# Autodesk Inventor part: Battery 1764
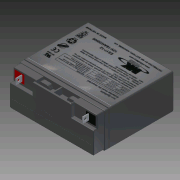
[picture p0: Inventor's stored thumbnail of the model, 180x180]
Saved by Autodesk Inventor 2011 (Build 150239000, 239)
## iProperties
Created: 2008-01
Part Number: Battery 1764
Document SubType Name: Modeling
Designer: rlindsay
Density: 1 g/cm^3
Author: rlindsay
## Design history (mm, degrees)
sketch "Sketch1"
  geometry: L1 (-28.148, 47.877)-(149.652, 47.877); L2 (149.652, 47.877)-(149.652, -25.148); L3 (149.652, -25.148)-(-28.148, -25.148); L4 (-28.148, -25.148)-(-28.148, 47.877)
  constraints: 8 end point, 2 parallel, 1 horizontal, 1 perpendicular
  dimensions: "d0" = 73.025 distance of L3.end L1.start; "d1" = 177.8 distance of L2.end L3.end
extrude "Extrusion1" new body sketch "Sketch1" distance "d2" = 165.1; taper "d3" = 0 deg
workplane "Work Plane1"
sketch "Sketch6"
  geometry: L1 (177.8, 0)-(177.8, -152.4); L2 (0, 0)-(0, -152.4); L3 (177.8, -128.392)-(-149.757, -128.392); L4 (-149.757, -128.392)-(-149.757, 18.237); L5 (-149.757, 18.237)-(177.8, 18.237); L6 (177.8, 18.237)-(177.8, -128.392); 1 other entity
  constraints: 4 end point, 2 other
  dimensions: "d70" = 180 deg angle of L1 L6
feature "Decal2" sketch "Sketch6"
sketch "Sketch7"
  geometry: L1 (177.8, 0)-(177.8, -165.1) reference; L2 (0, 0)-(0, -165.1) reference; L3 (177.8, -135.89)-(0, -135.89); L4 (0, -135.89)-(0, -134.112); L5 (0, -134.112)-(177.8, -134.112); L6 (177.8, -134.112)-(177.8, -135.89); L7 (0, -165.1)-(177.8, -165.1) reference; L8 (0, 0)-(177.8, 0) reference
  constraints: 8 end point, 2 parallel, 2 point on line, 1 horizontal, 1 perpendicular
  dimensions: "d99" = 1.778 distance between parallel lines of L5 L3
extrude "Extrusion5" cut sketch "Sketch7" distance "d101" = 1.778; taper "d102" = 0 deg
sketch "Sketch8"
  geometry: L1 (0, 0)-(165.1, 0) reference; L2 (135.89, 73.025)-(135.89, 71.247) reference; L3 (134.112, 73.025)-(135.89, 73.025); L4 (135.89, 73.025)-(135.89, 0); L5 (135.89, 0)-(134.112, 0); L6 (134.112, 0)-(134.112, 73.025)
  constraints: 8 end point, 2 parallel, 1 horizontal, 1 perpendicular, 1 point on line
  dimensions: "d103" = 0 distance between parallel lines of L4 L2
extrude "Extrusion6" cut sketch "Sketch8" distance "d104" = 1.778; taper "d105" = 0 deg
sketch "Sketch9"
  geometry: L1 (0, 135.89)-(1.778, 135.89) reference; L2 (177.8, 0)-(177.8, 165.1) reference; L3 (0, 134.112)-(177.8, 134.112); L4 (177.8, 134.112)-(177.8, 135.89); L5 (177.8, 135.89)-(0, 135.89); L6 (0, 135.89)-(0, 134.112)
  constraints: 8 end point, 2 parallel, 1 horizontal, 1 perpendicular, 1 point on line
  dimensions: "d106" = 0 distance between parallel lines of L5 L1
extrude "Extrusion7" cut sketch "Sketch9" distance "d107" = 1.778; taper "d108" = 0 deg
sketch "Sketch10"
  geometry: L1 (-135.89, 73.025)-(-134.112, 73.025); L2 (-134.112, 73.025)-(-134.112, 0); L3 (-134.112, 0)-(-135.89, 0); L4 (-135.89, 0)-(-135.89, 73.025)
  constraints: 8 end point, 2 parallel, 1 horizontal, 1 perpendicular
extrude "Extrusion8" cut sketch "Sketch10" distance "d109" = 1.778; taper "d110" = 0 deg
sketch "Sketch11"
  geometry: L1 (177.8, 29.21)-(0, 29.21) reference; L2 (0, 29.21)-(0, 0) reference; L3 (177.8, 29.21)-(177.8, 0) reference; L4 (127, 21.336)-(90.17, 21.336); L5 (90.17, 21.336)-(90.17, 0); L6 (90.17, 0)-(127, 0); L7 (127, 0)-(127, 21.336); L8 (87.63, 0)-(50.8, 0); L9 (50.8, 0)-(50.8, 21.336); L10 (50.8, 21.336)-(87.63, 21.336); L11 (87.63, 21.336)-(87.63, 0); L12 (0, 0)-(177.8, 0) reference
  constraints: 16 end point, 4 parallel, 2 horizontal, 2 perpendicular
  dimensions: "d111" = 7.874 distance between parallel lines of L1 L10; "d112" = 7.874 distance between parallel lines of L1 L4; "d113" = 50.8 distance between parallel lines of L3 L7; "d115" = 0 distance between parallel lines of L6 L8; "d116" = 50.8 distance between parallel lines of L9 L2; "d117" = 36.83 distance of L8.start L8.end; "d121" = 36.83 distance between parallel lines of L5 L7; "d122" = 0 distance between parallel lines of L12 L8
extrude "Extrusion9" cut sketch "Sketch11" distance "d119" = 13.97; taper "d120" = 0 deg
sketch "Sketch13"
  geometry: L1 (36.83, -13.97)-(0, -13.97) reference; L2 (36.83, 0)-(36.83, -13.97) reference; L3 (0, 0)-(36.83, 0) reference; L4 (0, 0)-(0, -13.97) reference; L5 (-49.276, -1.524)-(125.476, -1.524); L6 (125.476, -1.524)-(125.476, -71.501); L7 (125.476, -71.501)-(-49.276, -71.501); L8 (-49.276, -71.501)-(-49.276, -1.524); L9 (127, 0)-(127, -73.025) reference; L10 (127, -73.025)-(-50.8, -73.025) reference; L11 (-50.8, -73.025)-(-50.8, 0) reference; L12 (-50.8, 0)-(127, 0); L13 (127, 0)-(127, -73.025); L14 (127, -73.025)-(-50.8, -73.025); L15 (-50.8, -73.025)-(-50.8, 0)
  constraints: 16 end point, 4 parallel, 2 horizontal, 2 perpendicular
  dimensions: "d123" = 1.524 distance between parallel lines of L3 L5; "d124" = 1.524 distance between parallel lines of L9 L6; "d125" = 1.524 distance between parallel lines of L10 L7; "d126" = 1.524 distance between parallel lines of L11 L8; "d127" = 0 distance between parallel lines of L9 L13
extrude "Extrusion10" cut sketch "Sketch13" stored distance "d128" = 7.62; taper "d129" = 0 deg
sketch "Sketch14"
  geometry: L1 (148.128, -23.624)-(148.128, 46.353) reference; L2 (148.128, 46.353)-(98.852, 46.353) reference; L3 (-26.624, 46.353)-(20.366, 46.353); L4 (20.366, 46.353)-(20.366, 21.715); L5 (20.366, 21.715)-(-26.624, 21.715); L6 (-26.624, 21.715)-(-26.624, 46.353); L7 (101.138, 46.353)-(148.128, 46.353); L8 (148.128, 46.353)-(148.128, 21.715); L9 (148.128, 21.715)-(101.138, 21.715); L10 (101.138, 21.715)-(101.138, 46.353)
  constraints: 16 end point, 4 parallel, 2 horizontal, 2 perpendicular
  dimensions: "d130" = 46.99 distance of L4.end L5.end; "d131" = 24.638 distance of L3.end L4.end; "d132" = 0 distance between parallel lines of L2 L7; "d133" = 0 distance between parallel lines of L1 L8; "d134" = 24.638 distance of L9.end L7.start; "d135" = 46.99 distance of L8.end L9.end
extrude "Extrusion11" cut sketch "Sketch14" distance "d136" = 7.239; taper "d137" = 0 deg
sketch "Sketch15"
  geometry: L1 (-26.624, 46.353)-(20.366, 46.353) reference; L2 (-26.624, 21.715)-(-26.624, 46.353) reference; L3 (-23.322, 43.051)-(-3.002, 43.051); L4 (-3.002, 43.051)-(-3.002, 25.271); L5 (-3.002, 25.271)-(-23.322, 25.271); L6 (-23.322, 25.271)-(-23.322, 43.051); L7 (148.128, 46.353)-(148.128, 21.715) reference; L8 (101.138, 46.353)-(148.128, 46.353) reference
  constraints: 8 end point, 2 parallel, 1 horizontal, 1 perpendicular
  dimensions: "d138" = 3.302 distance between parallel lines of L1 L3; "d139" = 20.32 distance of L4.end L5.end; "d140" = 3.302 distance between parallel lines of L2 L6; "d141" = 17.78 distance of L3.end L4.end
extrude "Extrusion12" cut sketch "Sketch15" distance "d146" = 0.254; taper "d147" = 0 deg
sketch "Sketch16"
  geometry: L1 (148.128, 46.353)-(148.128, 21.715) reference; L2 (124.506, 25.017)-(144.826, 25.017); L3 (144.826, 25.017)-(144.826, 42.797); L4 (144.826, 42.797)-(124.506, 42.797); L5 (124.506, 42.797)-(124.506, 25.017); L6 (-26.37, 46.099)-(147.874, 46.099) reference
  constraints: 8 end point, 2 parallel, 1 horizontal, 1 perpendicular
  dimensions: "d148" = 3.302 distance between parallel lines of L6 L4; "d149" = 3.302 distance between parallel lines of L1 L3; "d150" = 17.78 distance of L4.end L2.start; "d151" = 20.32 distance of L3.end L4.end
extrude "Extrusion13" cut sketch "Sketch16" distance "d152" = 0.0254; taper "d153" = 0 deg
sketch "Sketch17"
  geometry: L1 (101.138, 46.353)-(98.852, 46.353) reference; L2 (62.022, 33.907)-(62.022, 46.353) reference; L3 (59.482, 46.353)-(59.482, 33.907) reference; L4 (22.652, 46.353)-(20.366, 46.353) reference; L5 (22.652, 33.907)-(40.432, 33.907); L6 (40.432, 33.907)-(40.432, 28.573); L7 (40.432, 28.573)-(22.652, 28.573); L8 (22.652, 28.573)-(22.652, 33.907); L9 (98.852, 33.907)-(81.072, 33.907); L10 (81.072, 33.907)-(81.072, 28.573); L11 (81.072, 28.573)-(98.852, 28.573); L12 (98.852, 28.573)-(98.852, 33.907)
  constraints: 16 end point, 4 parallel, 2 horizontal, 2 perpendicular
  dimensions: "d157" = 17.78 distance between parallel lines of L4 L7; "d158" = 19.05 distance between parallel lines of L3 L6; "d159" = 17.78 distance between parallel lines of L1 L11; "d160" = 19.05 distance between parallel lines of L2 L10
extrude "Extrusion14" cut sketch "Sketch17" stored distance "d161" = 25.4; taper "d162" = 0 deg
sketch "Sketch18"
  geometry: L1 (-26.624, 21.715)-(-26.624, -23.624) reference; L2 (-26.624, -23.624)-(148.128, -23.624) reference; L3 (148.128, -23.624)-(148.128, 21.715) reference; L4 (145.334, -5.844)-(-23.83, -5.844); L5 (-23.83, -5.844)-(-23.83, 18.921); L6 (-23.83, 18.921)-(145.334, 18.921); L7 (145.334, 18.921)-(145.334, -5.844)
  constraints: 8 end point, 2 parallel, 1 horizontal, 1 perpendicular
  dimensions: "d163" = 2.794 distance between parallel lines of L1 L5; "d164" = 2.794 distance between parallel lines of L3 L7; "d165" = 17.78 distance between parallel lines of L2 L4; "d166" = 24.765 distance between parallel lines of L4 L6
extrude "Extrusion15" cut sketch "Sketch18" distance "d167" = 0.127; taper "d168" = 0 deg
sketch "Sketch19"
  geometry: L1 (62.889, 3.821)-(38.353, 3.821); L2 (38.353, 3.821)-(38.353, 8.511); L3 (38.353, 8.511)-(62.889, 8.511); L4 (62.889, 8.511)-(62.889, 3.821)
  constraints: 2 other
extrude "Extrusion16" cut sketch "Sketch19" distance "d169" = 0.127; taper "d170" = 0 deg
sketch "Sketch20"
  geometry: L1 (50.8, -1.524)-(50.8, -19.304) reference; L2 (87.63, -1.524)-(87.63, -13.97) reference; L3 (0, 0)-(177.8, 0) reference; L4 (70.739, -21.658)-(52.705, -21.658); L5 (54.61, -5.842)-(70.739, -5.842); L6 (70.739, -5.842)-(70.739, -21.658); L7 (109.22, -19.304)-(127, -19.304) reference; L8 (125.095, -5.842)-(125.095, -19.304); L9 (125.095, -19.304)-(107.061, -19.304); L10 (50.8, -19.304)-(68.58, -19.304) reference; L11 (48.266, -11.928)-(48.266, -19.304); L12 (48.266, -19.304)-(50.8, -19.304); L13 (48.266, -19.304)-(70.739, -19.304); A1 r 6.35 centre (54.61, -12.192) between (54.912, -5.849) and (48.266, -11.928)
  constraints: 16 end point, 3 perpendicular, 3 point on circle, 3 point on line, 2 collinear, 1 centre point, 1 horizontal, 1 parallel
  dimensions: "d171" = 16.891 distance between parallel lines of L2 L6; "d173" = 5.842 distance between parallel lines of L3 L5; "d185" = 6.35 radius of A1; "d186" = 6.35 distance from line of L5 A1.centre; "d187" = 3.81 distance from line of L1 A1.centre
extrude "Extrusion17" join sketch "Sketch20" distance "d176" = 8.128; taper "d177" = 0 deg
sketch "Sketch21"
  geometry: L1 (22.652, 46.353)-(98.852, 46.353); L2 (98.852, 46.353)-(98.852, 28.573); L3 (98.852, 28.573)-(22.652, 28.573); L4 (22.652, 28.573)-(22.652, 46.353)
  constraints: 8 end point, 2 parallel, 1 horizontal, 1 perpendicular
extrude "Extrusion18" join sketch "Sketch21" distance "d178" = 3.048; taper "d179" = 0 deg
fillet "Fillet4" dims "d181" = 6.35
workplane "Work Plane2"
mirror "Mirror1"
fillet "Fillet5" dims "d189" = 6.35
fillet "Fillet6" dims "d190" = 2.54
fillet "Fillet7" dims "d191" = 1.27
sketch "Sketch23"
  geometry: L1 (-3.002, 43.051)-(-3.002, 25.271) reference; L2 (-26.37, 46.099)-(147.874, 46.099) reference; C1 r 3.81 at (7.158, 34.669); C2 r 4.28 at (112.672, 32.669)
  constraints: 2 centre point
  dimensions: "d192" = 11.43 distance from line of L2 C1.centre; "d193" = 10.16 distance from line of L1 C1.centre; "d194" = 7.62 diameter of C1
extrude "Extrusion19" cut sketch "Sketch23" distance "d195" = 0.0508; taper "d196" = 0 deg
mirror "Mirror2"
sketch "Sketch24"
  geometry: L1 (-0.635, 5.715)-(-0.635, 0.635); L2 (-0.635, 0.635)-(-5.715, 0.635); L3 (-5.715, 0.635)-(-5.715, -0.635); L4 (-5.715, -0.635)-(-0.635, -0.635); L5 (-0.635, -0.635)-(-0.635, -5.715); L6 (-0.635, -5.715)-(0.635, -5.715); L7 (0.635, -5.715)-(0.635, -0.635); L8 (0.635, -0.635)-(5.715, -0.635); L9 (5.715, -0.635)-(5.715, 0.635); L10 (5.715, 0.635)-(0.635, 0.635); L11 (0.635, 0.635)-(0.635, 5.715); L12 (0.635, 5.715)-(-0.635, 5.715); C1 r 3.81 at (0, 0) reference
  constraints: 24 end point, 8 parallel, 2 collinear, 1 perpendicular, 1 vertical
  dimensions: "d201" = 1.27 distance between parallel lines of L4 L2; "d202" = 1.27 distance between parallel lines of L8 L10 (= d201); "d203" = 1.27 distance between parallel lines of L5 L7 (= d201); "d204" = 1.27 distance between parallel lines of L11 L1 (= d201); "d205" = 5.08 distance of L1.end L2.end; "d206" = 5.08 distance of L7.end L8.end; "d207" = 5.08 distance of L3.end L4.end; "d208" = 5.08 distance of L1.start L1.end; "d209" = 5.08 distance of L4.end L5.end; "d210" = 0.635 distance from line of C1.centre L11; "d211" = 0.635 distance from line of C1.centre L10; "d212" = 5.08 distance of L10.end L11.end
extrude "Extrusion20" join sketch "Sketch24" distance "d213" = 0.0254; taper "d214" = 0 deg
sketch "Sketch25"
  geometry: L1 (-5.372, 0.635)-(6.193, 0.635); L2 (6.193, 0.635)-(6.193, -0.635); L3 (6.193, -0.635)-(-5.372, -0.635); L4 (-5.372, -0.635)-(-5.372, 0.635); C1 r 3.81 at (0, 0) reference
  constraints: 8 end point, 2 parallel, 1 horizontal, 1 perpendicular
  dimensions: "d215" = 1.27 distance of L3.end L1.start; "d216" = 0.635 distance from line of C1.centre L3
extrude "Extrusion21" join sketch "Sketch25" distance "d217" = 0.0254; taper "d218" = 0 deg
sketch "Sketch26"
  geometry: L1 (-126.792, 30.097)-(5.288, 30.097); L2 (17.988, 17.397)-(17.988, 5.332); L3 (5.288, -7.368)-(-126.792, -7.368); L4 (-139.492, 5.332)-(-139.492, 17.397); L5 (28.148, -22.608)-(28.148, 45.337) reference; L6 (-149.652, 45.337)-(-149.652, -22.608) reference; L7 (25.608, 47.877)-(-147.112, 47.877) reference; L8 (-147.112, -25.148)-(25.608, -25.148) reference; A1 r 12.7 centre (-126.792, 17.397) between (-126.792, 30.097) and (-139.246, 14.91); A2 r 12.7 centre (-126.792, 5.332) between (-139.437, 6.508) and (-126.792, -7.368); A3 r 12.7 centre (5.288, 5.332) between (5.288, -7.368) and (17.874, 7.033); A4 r 12.7 centre (5.288, 17.397) between (17.64, 14.443) and (5.288, 30.097)
  constraints: 12 point on circle, 8 end point, 4 centre point, 2 parallel, 1 horizontal, 1 perpendicular
  dimensions: "d219" = 10.16 distance between parallel lines of L5 L2; "d220" = 10.16 distance between parallel lines of L6 L4; "d221" = 17.78 distance between parallel lines of L7 L1; "d222" = 17.78 distance between parallel lines of L8 L3; "d223" = 12.7 distance from line of L4 A1.centre (= d225); "d224" = 12.7 distance from line of L1 A1.centre (= d225); "d225" = 12.7 radius of A1; "d226" = 12.7 distance from line of L4 A2.centre (= d225); "d227" = 12.7 distance from line of L3 A2.centre (= d225); "d228" = 12.7 radius of A2 (= d225); "d229" = 12.7 distance from line of L1 A4.centre (= d225); "d230" = 12.7 distance from line of L2 A4.centre (= d225); "d231" = 12.7 radius of A4 (= d225); "d232" = 12.7 distance from line of L2 A3.centre (= d225); "d233" = 12.7 distance from line of L3 A3.centre (= d225); "d234" = 12.7 radius of A3 (= d225)
extrude "Extrusion22" cut sketch "Sketch26" distance "d235" = 0.127; taper "d236" = 0 deg
sketch "Sketch27"
  geometry: L1 (-139.492, 17.397)-(-139.492, 5.332) reference; L2 (17.988, 5.332)-(17.988, 17.397) reference; L3 (-100.798, 45.083)-(-145.588, 45.083) reference; L4 (25.608, -22.608)-(-147.112, -22.608) reference; C1 r 1.905 at (-119.172, 11.237); C2 r 1.905 at (-89.962, 11.237); C3 r 1.905 at (-60.752, 11.237); C4 r 1.905 at (-31.542, 11.237); C5 r 1.905 at (-2.332, 11.237)
  constraints: 5 centre point, 4 equal radius, 4 horizontal alignment
  dimensions: "d237" = 3.81 diameter of C1; "d238" = 33.8455 distance from line of L3 C1.centre; "d239" = 33.8455 distance from line of L4 C1.centre (derived); "d240" = 29.21 distance of C2.centre C1.centre; "d241" = 29.21 distance of C3.centre C2.centre (= d240); "d242" = 29.21 distance of C4.centre C3.centre (= d240); "d243" = 29.21 distance of C5.centre C4.centre (= d240); "d244" = 20.32 distance from line of C1.centre L1; "d245" = 20.32 distance from line of L2 C5.centre (derived)
hole "Hole1" sketch "Sketch27" at (-119.172, 11.237), (-89.962, 11.237), (-60.752, 11.237), (-31.542, 11.237), (-2.332, 11.237) diameter "d246" = 3.81; stored, may be unused: countersink angle "d250" = 82 deg, drill point angle "d252" = 120 deg; dims "d247" = 12.7, "d248" = 9.525, "d249" = 6.35, "d251" = 0.0254
sketch "Sketch28"
  geometry: L1 (0, 0)-(169.672, 0) reference; L2 (18.542, 21.336)-(59.436, 21.336); L3 (59.436, 21.336)-(59.436, 0); L4 (59.436, 0)-(18.542, 0); L5 (18.542, 0)-(18.542, 21.336); L6 (61.976, 21.336)-(85.725, 21.336); L7 (85.725, 21.336)-(85.725, 0); L8 (85.725, 0)-(61.976, 0); L9 (61.976, 0)-(61.976, 21.336); L10 (169.672, 21.336)-(0, 21.336) reference; L11 (-2.54, 20.066)-(-2.54, 0) reference
  constraints: 16 end point, 4 parallel, 2 horizontal, 2 perpendicular
  dimensions: "d253" = 0 distance between parallel lines of L10 L2; "d254" = 0 distance between parallel lines of L10 L6; "d255" = 21.082 distance between parallel lines of L11 L5; "d256" = 40.894 distance of L3.end L4.end; "d257" = 2.54 distance between parallel lines of L9 L3; "d258" = 0 distance between parallel lines of L1 L4; "d259" = 23.749 distance of L7.end L8.end
extrude "Extrusion23" cut sketch "Sketch28" distance "d260" = 13.97; taper "d261" = 0 deg
sketch "Sketch29"
  geometry: L1 (18.542, 21.336)-(18.542, 0) reference; L2 (18.542, 0)-(59.436, 0) reference; L3 (59.436, 0)-(59.436, 21.336) reference; L4 (18.542, 21.336)-(35.306, 21.336); L5 (35.306, 21.336)-(35.306, 0); L6 (35.306, 0)-(18.542, 0); L7 (18.542, 0)-(18.542, 21.336); L8 (76.835, 21.336)-(85.725, 21.336); L9 (85.725, 21.336)-(85.725, 0); L10 (85.725, 0)-(76.835, 0); L11 (76.835, 0)-(76.835, 21.336); L12 (61.976, 21.336)-(85.725, 21.336) reference; L13 (85.725, 20.066)-(85.725, 0) reference; L14 (171.196, 0)-(-1.524, 0) reference
  constraints: 16 end point, 4 parallel, 2 horizontal, 2 perpendicular, 1 point on line
  dimensions: "d262" = 24.13 distance between parallel lines of L3 L5; "d265" = 0 distance between parallel lines of L12 L8; "d266" = 0 distance between parallel lines of L13 L9; "d267" = 0 distance between parallel lines of L14 L10; "d268" = 8.89 distance between parallel lines of L9 L11
extrude "Extrusion24" cut sketch "Sketch29" distance "d263" = 3.81; taper "d264" = 0 deg
sketch "Sketch30"
  geometry: L1 (87.249, 0.254)-(87.249, 18.034) reference; L2 (87.249, 5.08)-(75.819, 5.08); L3 (75.819, 5.08)-(75.819, 18.669); L4 (75.819, 18.669)-(87.249, 18.669); L5 (87.249, 18.669)-(87.249, 5.08); L6 (0, -1.27)-(172.72, -1.27) reference
  constraints: 8 end point, 2 parallel, 1 horizontal, 1 perpendicular, 1 point on line
  dimensions: "d269" = 11.43 distance of L2.start L2.end; "d270" = 6.35 distance between parallel lines of L6 L2
extrude "Extrusion25" join sketch "Sketch30" distance "d271" = 7.62; taper "d272" = 0 deg
fillet "Fillet8" dims "d273" = 6.35
sketch "Sketch31"
  geometry: L1 (60.96, 0.254)-(60.96, 14.224) reference; L2 (20.066, 18.034)-(36.83, 18.034) reference; L3 (20.066, 0.254)-(20.066, 18.034) reference; L4 (16.611, 18.034)-(16.611, 6.394); L5 (23.876, 4.064)-(41.91, 4.064); L6 (41.91, 4.064)-(41.91, 18.034); L7 (41.91, 18.034)-(25.468, 18.034); L8 (41.91, 18.034)-(17.526, 18.034); L9 (17.526, 18.034)-(17.526, 10.414); A1 r 6.35 centre (23.876, 10.414) between (17.526, 10.414) and (23.876, 4.064)
  constraints: 12 end point, 3 perpendicular, 3 point on circle, 2 point on line, 1 centre point, 1 parallel
  dimensions: "d274" = 19.05 distance between parallel lines of L6 L1; "d275" = 6.35 radius of A1; "d276" = 3.81 distance from line of L3 A1.centre
extrude "Extrusion26" join sketch "Sketch31" distance "d278" = 7.62; taper "d279" = 0 deg
fillet "Fillet9" dims "d280" = 6.35
fillet "Fillet10" dims "d281" = 0.508
mirror "Mirror3"
sketch "Sketch33"
  geometry: L1 (-5.542, -5.844)-(127.046, -5.844); L2 (127.046, -5.844)-(127.046, -23.624); L3 (127.046, -23.624)-(-5.542, -23.624); L4 (-5.542, -23.624)-(-5.542, -5.844); L5 (147.112, -23.878)-(-25.608, -23.878) reference; L6 (83.612, -23.624)-(86.152, -23.624) reference
  constraints: 8 end point, 2 parallel, 1 horizontal, 1 perpendicular
  dimensions: "d288" = 0 distance between parallel lines of L6 L3
extrude "Extrusion28" join sketch "Sketch33" distance "d285" = 3.81; taper "d286" = 0 deg
fillet "Fillet11" dims "d287" = 1.27
sketch "Sketch35"
  geometry: L1 (-3.002, 25.271)-(-3.002, 43.051) reference; L2 (-3.002, 43.051)-(-23.322, 43.051) reference; L3 (-9.606, 40.511)-(-7.701, 40.511); L4 (-7.701, 40.511)-(-7.701, 28.573); L5 (-7.701, 28.573)-(-9.606, 28.573); L6 (-9.606, 28.573)-(-9.606, 40.511)
  constraints: 8 end point, 2 parallel, 1 horizontal, 1 perpendicular
  dimensions: "d293" = 1.905 distance between parallel lines of L4 L6; "d294" = 11.938 distance between parallel lines of L5 L3; "d295" = 2.54 distance between parallel lines of L2 L3; "d296" = 4.699 distance between parallel lines of L1 L4
extrude "Extrusion29" join sketch "Sketch35" distance "d297" = 12.7; taper "d298" = 0 deg
sketch "Sketch36"
  geometry: L1 (0, 11.938)-(12.7, 11.938) reference; L2 (0, 0)-(12.7, 0) reference; L3 (12.7, 0)-(12.7, 11.938) reference; C1 r 2.794 at (7.366, 5.969)
  constraints: 1 centre point
  dimensions: "d299" = 5.969 distance from line of L1 C1.centre; "d300" = 5.969 distance from line of L2 C1.centre (derived); "d305" = 5.588 diameter of C1; "d306" = 5.334 distance from line of L3 C1.centre
extrude "Extrusion30" cut sketch "Sketch36" distance "d301" = 11.43; taper "d302" = 0 deg
mirror "Mirror4"
body "Solid1"
node "Image23"
other parameters: "d188" = -1.27, "d197" = 1.27, "d198" = 1.27, "d199" = 0.635, "d200" = 0.635
